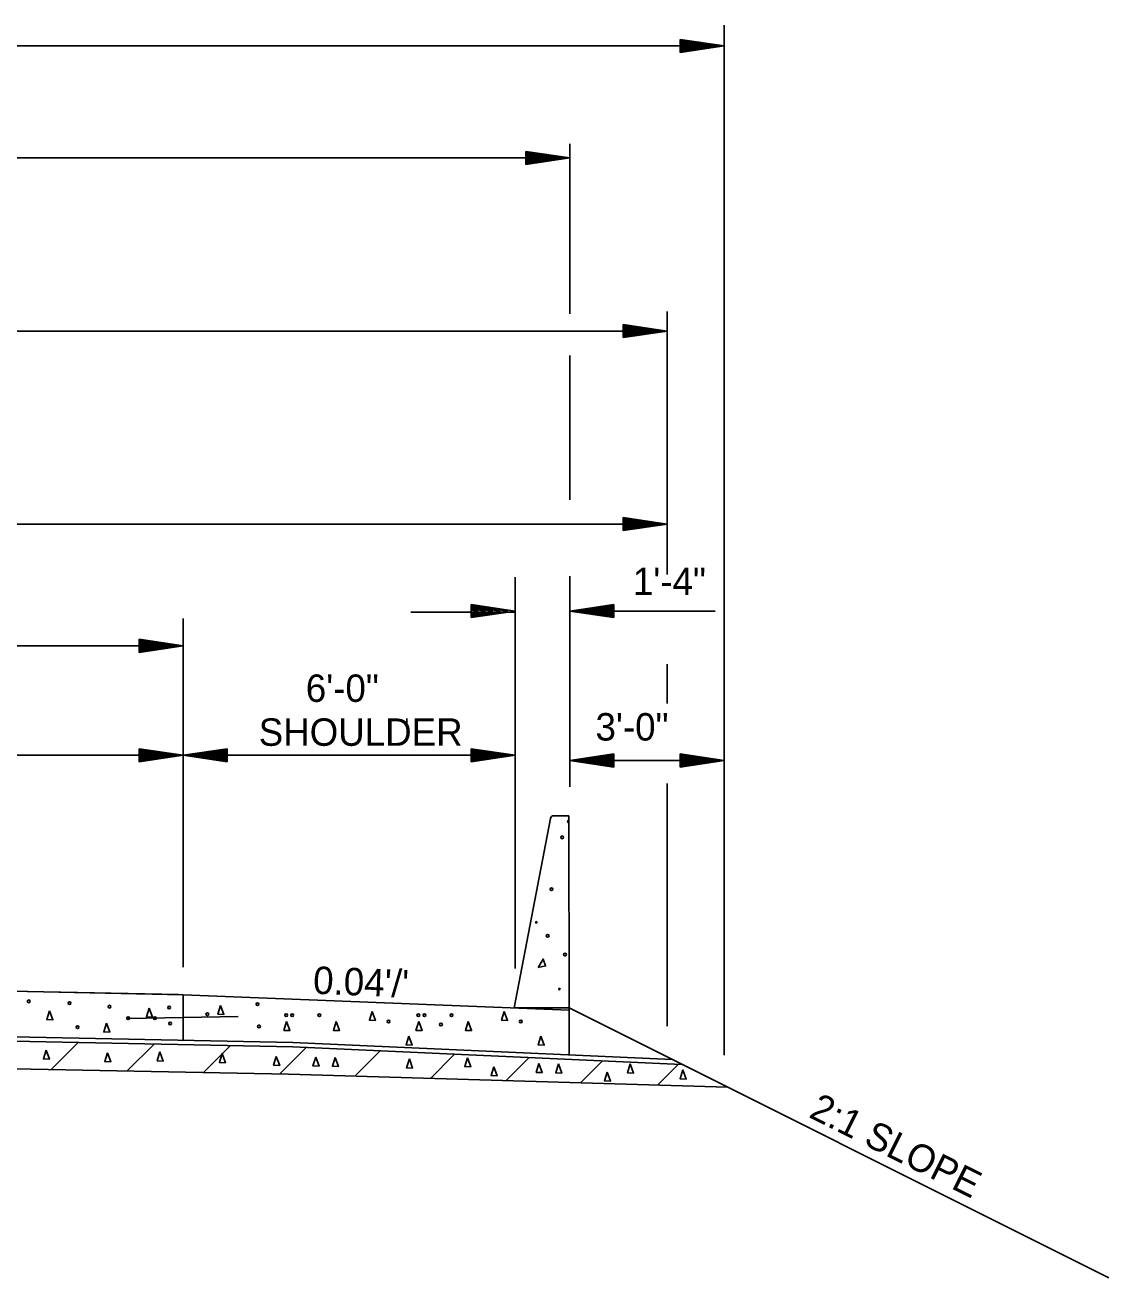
# Model space of a CAD drawing. Extents: x 60325 to 61047, y 53669 to 53767.
# Drawn here: x 60974.17 to 60993.92, y 53717.87 to 53740.69 of the extents above; entities that cross this region are included whole.
import ezdxf

# ---------------------------------------------------------------- set-up
doc = ezdxf.new("R2010")
doc.units = 0
doc.layers.add('R_Border', color=7, linetype='Continuous')
doc.layers.add('R_Border Prem', color=7, linetype='Continuous')

msp = doc.modelspace()

# ---------------------------------------------------------------- linework, layer by layer
at = {"layer": 'R_Border'}
for p, q in [((60977.051, 53727.969), (60977.051, 53729.882)), ((60977.051, 53729.382), (60953.051, 53729.382)), ((60976.251, 53729.502), (60977.051, 53729.382)), ((60976.251, 53729.502), (60976.251, 53729.262)), ((60976.251, 53729.482), (60976.917, 53729.382)), ((60976.251, 53729.461), (60976.78, 53729.382)), ((60976.251, 53729.441), (60976.646, 53729.382)), ((60976.251, 53729.421), (60976.511, 53729.382)), ((60976.251, 53729.401), (60976.377, 53729.382)), ((60976.251, 53729.262), (60977.051, 53729.382)), ((60976.251, 53729.343), (60976.511, 53729.382)), ((60976.251, 53729.302), (60976.78, 53729.382)), ((60976.251, 53729.282), (60976.917, 53729.382)), ((60976.251, 53729.322), (60976.646, 53729.382)), ((60976.251, 53729.363), (60976.377, 53729.382)), ((60977.051, 53723.526), (60977.051, 53727.969)), ((60981.128, 53727.969), (60981.128, 53728.06)), ((60976.251, 53727.508), (60977.051, 53727.388)), ((60976.251, 53727.508), (60976.251, 53727.268)), ((60976.251, 53727.488), (60976.917, 53727.388)), ((60976.251, 53727.467), (60976.78, 53727.388)), ((60977.051, 53727.388), (60953.051, 53727.388)), ((60976.251, 53727.447), (60976.646, 53727.388)), ((60976.251, 53727.427), (60976.511, 53727.388)), ((60976.251, 53727.407), (60976.377, 53727.388)), ((60976.251, 53727.268), (60977.051, 53727.388)), ((60976.251, 53727.349), (60976.511, 53727.388)), ((60976.251, 53727.308), (60976.78, 53727.388)), ((60976.251, 53727.288), (60976.917, 53727.388)), ((60976.251, 53727.328), (60976.646, 53727.388)), ((60976.251, 53727.369), (60976.377, 53727.388)), ((60977.051, 53723.81), (60977.051, 53726.846)), ((60977.051, 53723.026), (60977.051, 53722.193)), ((60977.051, 53722.61), (60976.051, 53722.59)), ((60978.051, 53722.63), (60977.051, 53722.61))]:
    msp.add_line(p, q, dxfattribs=at)
msp.add_lwpolyline([(60953.053, 53723.506), (60976.967, 53723.028), (60977.051, 53723.025)], dxfattribs=at)
at = {"layer": 'R_Border Prem'}
for p, q in [((60986.91, 53725.154), (60986.91, 53740.691)), ((60986.91, 53740.31), (60945.245, 53740.31)), ((60986.11, 53740.43), (60986.91, 53740.31)), ((60986.11, 53740.43), (60986.11, 53740.19)), ((60986.11, 53740.41), (60986.777, 53740.31)), ((60986.11, 53740.39), (60986.639, 53740.31)), ((60986.11, 53740.37), (60986.506, 53740.31)), ((60986.11, 53740.349), (60986.37, 53740.31)), ((60986.11, 53740.329), (60986.237, 53740.31)), ((60986.11, 53740.19), (60986.91, 53740.31)), ((60986.11, 53740.271), (60986.37, 53740.31)), ((60986.11, 53740.231), (60986.639, 53740.31)), ((60986.11, 53740.21), (60986.777, 53740.31)), ((60986.11, 53740.251), (60986.506, 53740.31)), ((60986.11, 53740.291), (60986.237, 53740.31)), ((60984.098, 53735.427), (60984.098, 53738.527)), ((60984.098, 53738.269), (60948.056, 53738.269)), ((60983.298, 53738.389), (60984.098, 53738.269)), ((60983.298, 53738.389), (60983.298, 53738.149)), ((60983.298, 53738.369), (60983.965, 53738.269)), ((60983.298, 53738.349), (60983.827, 53738.269)), ((60983.298, 53738.329), (60983.694, 53738.269)), ((60983.298, 53738.308), (60983.558, 53738.269)), ((60983.298, 53738.288), (60983.425, 53738.269)), ((60983.298, 53738.149), (60984.098, 53738.269)), ((60983.298, 53738.23), (60983.558, 53738.269)), ((60983.298, 53738.19), (60983.827, 53738.269)), ((60983.298, 53738.169), (60983.965, 53738.269)), ((60983.298, 53738.21), (60983.694, 53738.269)), ((60983.298, 53738.25), (60983.425, 53738.269)), ((60985.868, 53730.681), (60985.868, 53735.471)), ((60985.868, 53730.681), (60985.868, 53735.471)), ((60985.068, 53735.237), (60985.868, 53735.117)), ((60985.068, 53735.237), (60985.068, 53734.997)), ((60985.068, 53735.217), (60985.735, 53735.117)), ((60985.868, 53735.117), (60946.286, 53735.117)), ((60985.068, 53735.196), (60985.597, 53735.117)), ((60985.068, 53735.176), (60985.464, 53735.117)), ((60985.068, 53735.155), (60985.328, 53735.117)), ((60985.068, 53735.135), (60985.195, 53735.117)), ((60985.068, 53734.997), (60985.868, 53735.117)), ((60985.068, 53735.077), (60985.328, 53735.117)), ((60985.068, 53735.037), (60985.597, 53735.117)), ((60985.068, 53735.017), (60985.735, 53735.117)), ((60985.068, 53735.057), (60985.464, 53735.117)), ((60985.068, 53735.098), (60985.195, 53735.117)), ((60984.098, 53732.042), (60984.098, 53734.67)), ((60985.868, 53731.6), (60946.286, 53731.6)), ((60985.068, 53731.72), (60985.868, 53731.6)), ((60985.068, 53731.72), (60985.068, 53731.48)), ((60985.068, 53731.7), (60985.735, 53731.6)), ((60985.068, 53731.68), (60985.597, 53731.6)), ((60985.068, 53731.66), (60985.464, 53731.6)), ((60985.068, 53731.639), (60985.328, 53731.6)), ((60985.068, 53731.619), (60985.195, 53731.6)), ((60985.068, 53731.48), (60985.868, 53731.6)), ((60985.068, 53731.561), (60985.328, 53731.6)), ((60985.068, 53731.521), (60985.597, 53731.6)), ((60985.068, 53731.5), (60985.735, 53731.6)), ((60985.068, 53731.541), (60985.464, 53731.6)), ((60985.068, 53731.582), (60985.195, 53731.6)), ((60984.098, 53726.814), (60984.098, 53730.651)), ((60983.102, 53723.506), (60983.102, 53730.635)), ((60983.098, 53729.996), (60981.202, 53729.996)), ((60982.302, 53730.135), (60983.102, 53730.015)), ((60982.302, 53730.135), (60982.302, 53729.895)), ((60982.302, 53730.115), (60982.968, 53730.015)), ((60982.302, 53730.095), (60982.831, 53730.015)), ((60982.302, 53730.075), (60982.697, 53730.015)), ((60982.302, 53730.054), (60982.562, 53730.015)), ((60982.302, 53730.034), (60982.428, 53730.015)), ((60982.302, 53729.895), (60983.102, 53730.015)), ((60982.302, 53729.976), (60982.562, 53730.015)), ((60982.302, 53729.936), (60982.831, 53730.015)), ((60982.302, 53729.915), (60982.968, 53730.015)), ((60982.302, 53729.956), (60982.697, 53730.015)), ((60982.302, 53729.997), (60982.428, 53730.015)), ((60984.898, 53730.135), (60984.098, 53730.015)), ((60984.898, 53729.895), (60984.098, 53730.015)), ((60984.098, 53730.015), (60986.743, 53730.015)), ((60984.898, 53730.115), (60984.232, 53730.015)), ((60984.898, 53729.915), (60984.232, 53730.015)), ((60984.898, 53730.095), (60984.37, 53730.015)), ((60984.898, 53729.936), (60984.37, 53730.015)), ((60984.898, 53730.075), (60984.503, 53730.015)), ((60984.898, 53729.956), (60984.503, 53730.015)), ((60984.898, 53730.055), (60984.638, 53730.015)), ((60984.898, 53729.977), (60984.638, 53730.015)), ((60984.898, 53730.034), (60984.772, 53730.015)), ((60984.898, 53729.997), (60984.772, 53730.015)), ((60984.898, 53729.895), (60984.898, 53730.135)), ((60985.868, 53728.332), (60985.868, 53729.05)), ((60977.851, 53727.508), (60977.051, 53727.388)), ((60977.851, 53727.488), (60977.184, 53727.388)), ((60977.851, 53727.467), (60977.322, 53727.388)), ((60977.851, 53727.268), (60977.851, 53727.508)), ((60982.302, 53727.508), (60983.102, 53727.388)), ((60982.302, 53727.508), (60982.302, 53727.268)), ((60982.302, 53727.488), (60982.968, 53727.388)), ((60982.302, 53727.467), (60982.831, 53727.388)), ((60983.102, 53727.388), (60977.051, 53727.388)), ((60977.851, 53727.268), (60977.051, 53727.388)), ((60977.851, 53727.288), (60977.184, 53727.388)), ((60977.851, 53727.308), (60977.322, 53727.388)), ((60977.851, 53727.447), (60977.455, 53727.388)), ((60977.851, 53727.328), (60977.455, 53727.388)), ((60977.851, 53727.427), (60977.591, 53727.388)), ((60977.851, 53727.349), (60977.591, 53727.388)), ((60977.851, 53727.407), (60977.724, 53727.388)), ((60977.851, 53727.369), (60977.724, 53727.388)), ((60982.302, 53727.447), (60982.697, 53727.388)), ((60982.302, 53727.427), (60982.562, 53727.388)), ((60982.302, 53727.407), (60982.428, 53727.388)), ((60982.302, 53727.268), (60983.102, 53727.388)), ((60982.302, 53727.349), (60982.562, 53727.388)), ((60982.302, 53727.308), (60982.831, 53727.388)), ((60982.302, 53727.288), (60982.968, 53727.388)), ((60982.302, 53727.328), (60982.697, 53727.388)), ((60982.302, 53727.369), (60982.428, 53727.388)), ((60984.898, 53727.414), (60984.098, 53727.294)), ((60984.898, 53727.174), (60984.098, 53727.294)), ((60984.098, 53727.294), (60986.91, 53727.294)), ((60984.898, 53727.394), (60984.232, 53727.294)), ((60984.898, 53727.194), (60984.232, 53727.294)), ((60984.898, 53727.374), (60984.37, 53727.294)), ((60984.898, 53727.215), (60984.37, 53727.294)), ((60984.898, 53727.354), (60984.503, 53727.294)), ((60984.898, 53727.235), (60984.503, 53727.294)), ((60984.898, 53727.334), (60984.638, 53727.294)), ((60984.898, 53727.256), (60984.638, 53727.294)), ((60984.898, 53727.313), (60984.772, 53727.294)), ((60984.898, 53727.276), (60984.772, 53727.294)), ((60984.898, 53727.174), (60984.898, 53727.414)), ((60986.11, 53727.414), (60986.91, 53727.294)), ((60986.11, 53727.414), (60986.11, 53727.174)), ((60986.11, 53727.394), (60986.777, 53727.294)), ((60986.11, 53727.374), (60986.639, 53727.294)), ((60986.11, 53727.354), (60986.506, 53727.294)), ((60986.11, 53727.333), (60986.37, 53727.294)), ((60986.11, 53727.313), (60986.237, 53727.294)), ((60986.11, 53727.174), (60986.91, 53727.294)), ((60986.11, 53727.255), (60986.37, 53727.294)), ((60986.11, 53727.215), (60986.639, 53727.294)), ((60986.11, 53727.194), (60986.777, 53727.294)), ((60986.11, 53727.235), (60986.506, 53727.294)), ((60986.11, 53727.276), (60986.237, 53727.294)), ((60985.868, 53724.896), (60985.868, 53726.874)), ((60983.085, 53722.785), (60983.743, 53726.236)), ((60983.804, 53726.286), (60984.081, 53726.286)), ((60984.081, 53726.286), (60984.082, 53722.785)), ((60986.91, 53721.923), (60986.91, 53725.154)), ((60985.868, 53722.455), (60985.868, 53724.896)), ((60953.05, 53723.506), (60977.051, 53723.026)), ((60977.051, 53723.026), (60984.082, 53722.745)), ((60953.054, 53722.676), (60979.051, 53722.156)), ((60984.082, 53722.785), (60983.085, 53722.785)), ((60984.082, 53722.785), (60993.921, 53717.866)), ((60984.082, 53722.785), (60984.087, 53721.93)), ((60953.053, 53722.596), (60979.051, 53722.076)), ((60953.011, 53722.097), (60978.968, 53721.578)), ((60974.648, 53721.665), (60975.138, 53722.155)), ((60976.034, 53721.637), (60976.525, 53722.127)), ((60977.421, 53721.609), (60977.911, 53722.099)), ((60978.807, 53721.581), (60979.29, 53722.064)), ((60979.051, 53722.156), (60985.961, 53721.845)), ((60979.051, 53722.076), (60986.137, 53721.757)), ((60980.182, 53721.542), (60980.637, 53721.997)), ((60981.556, 53721.501), (60981.984, 53721.93)), ((60982.937, 53721.46), (60983.345, 53721.868)), ((60984.291, 53721.42), (60984.68, 53721.808)), ((60985.697, 53721.378), (60986.065, 53721.746)), ((60978.968, 53721.578), (60986.972, 53721.34))]:
    msp.add_line(p, q, dxfattribs=at)
for points in [[(60983.52, 53723.52), (60983.614, 53723.675), (60983.654, 53723.551), (60983.52, 53723.52)], [(60974.617, 53722.735), (60974.677, 53722.569), (60974.567, 53722.573), (60974.617, 53722.735)], [(60976.431, 53722.783), (60976.492, 53722.617), (60976.382, 53722.622), (60976.431, 53722.783)], [(60977.733, 53722.832), (60977.794, 53722.666), (60977.684, 53722.671), (60977.733, 53722.832)], [(60980.494, 53722.722), (60980.554, 53722.556), (60980.444, 53722.56), (60980.494, 53722.722)], [(60982.902, 53722.722), (60982.963, 53722.556), (60982.853, 53722.56), (60982.902, 53722.722)], [(60975.654, 53722.508), (60975.714, 53722.342), (60975.604, 53722.347), (60975.654, 53722.508)], [(60978.936, 53722.538), (60978.996, 53722.372), (60978.886, 53722.376), (60978.936, 53722.538)], [(60979.837, 53722.538), (60979.898, 53722.372), (60979.788, 53722.376), (60979.837, 53722.538)], [(60981.344, 53722.538), (60981.404, 53722.372), (60981.294, 53722.376), (60981.344, 53722.538)], [(60982.245, 53722.538), (60982.306, 53722.372), (60982.196, 53722.376), (60982.245, 53722.538)], [(60981.163, 53722.272), (60981.223, 53722.106), (60981.113, 53722.111), (60981.163, 53722.272)], [(60983.571, 53722.272), (60983.631, 53722.106), (60983.521, 53722.111), (60983.571, 53722.272)], [(60974.553, 53722.017), (60974.614, 53721.851), (60974.504, 53721.855), (60974.553, 53722.017)], [(60976.627, 53721.984), (60976.688, 53721.818), (60976.578, 53721.823), (60976.627, 53721.984)], [(60975.671, 53721.968), (60975.732, 53721.802), (60975.622, 53721.807), (60975.671, 53721.968)], [(60977.761, 53721.952), (60977.822, 53721.786), (60977.712, 53721.791), (60977.761, 53721.952)], [(60978.749, 53721.903), (60978.81, 53721.737), (60978.7, 53721.742), (60978.749, 53721.903)], [(60979.466, 53721.889), (60979.527, 53721.723), (60979.417, 53721.728), (60979.466, 53721.889)], [(60979.819, 53721.882), (60979.88, 53721.716), (60979.77, 53721.721), (60979.819, 53721.882)], [(60981.173, 53721.855), (60981.233, 53721.689), (60981.123, 53721.693), (60981.173, 53721.855)], [(60982.23, 53721.876), (60982.291, 53721.71), (60982.181, 53721.715), (60982.23, 53721.876)], [(60983.535, 53721.772), (60983.596, 53721.606), (60983.486, 53721.611), (60983.535, 53721.772)], [(60983.888, 53721.765), (60983.949, 53721.599), (60983.839, 53721.603), (60983.888, 53721.765)], [(60985.198, 53721.765), (60985.258, 53721.599), (60985.148, 53721.603), (60985.198, 53721.765)], [(60982.71, 53721.712), (60982.771, 53721.546), (60982.661, 53721.551), (60982.71, 53721.712)], [(60984.78, 53721.617), (60984.841, 53721.451), (60984.731, 53721.455), (60984.78, 53721.617)], [(60986.157, 53721.656), (60986.217, 53721.49), (60986.107, 53721.494), (60986.157, 53721.656)]]:
    msp.add_lwpolyline(points, dxfattribs=at)
for centre, radius in [((60983.959, 53725.893), 0.0254), ((60983.763, 53724.947), 0.0254), ((60983.486, 53724.344), 0.0127), ((60983.693, 53724.097), 0.0254), ((60984.009, 53723.756), 0.0254), ((60983.907, 53723.129), 0.0127), ((60974.237, 53722.905), 0.025), ((60974.982, 53722.873), 0.025), ((60975.711, 53722.808), 0.025), ((60976.796, 53722.792), 0.025), ((60977.492, 53722.669), 0.025), ((60978.404, 53722.855), 0.025), ((60978.929, 53722.655), 0.025), ((60979.039, 53722.651), 0.025), ((60979.533, 53722.651), 0.025), ((60981.337, 53722.655), 0.025), ((60981.447, 53722.651), 0.025), ((60981.941, 53722.651), 0.025), ((60975.128, 53722.435), 0.025), ((60976.051, 53722.597), 0.025), ((60976.537, 53722.597), 0.025), ((60976.813, 53722.5), 0.025), ((60978.433, 53722.449), 0.025), ((60980.795, 53722.538), 0.025), ((60981.749, 53722.482), 0.025), ((60983.203, 53722.538), 0.025)]:
    msp.add_circle(centre, radius, dxfattribs=at)
msp.add_arc((60984.08, 53726.182), 0.0254, 86.1643, 273.852, dxfattribs=at)
msp.add_ellipse((60983.804, 53726.224), major_axis=(0, 0.0619), ratio=0.9997, start_param=0, end_param=1.382575, dxfattribs=at)

# ---------------------------------------------------------------- texts
for s, p in [('1\'-4"', (60985.246, 53730.306)), ('6\'-0"', (60979.286, 53728.36)), ('3\'-0"', (60984.565, 53727.656)), ('SHOULDER', (60978.428, 53727.56))]:
    msp.add_text(s, height=0.5, dxfattribs=at).set_placement(p)
for s, rotation, p in [("0.04'/'", 357.7094, (60979.412, 53723.044)), ('2:1 SLOPE', 333.4349, (60988.433, 53720.804))]:
    msp.add_text(s, height=0.5, rotation=rotation, dxfattribs=at).set_placement(p)

doc.saveas('drawing.dxf')
